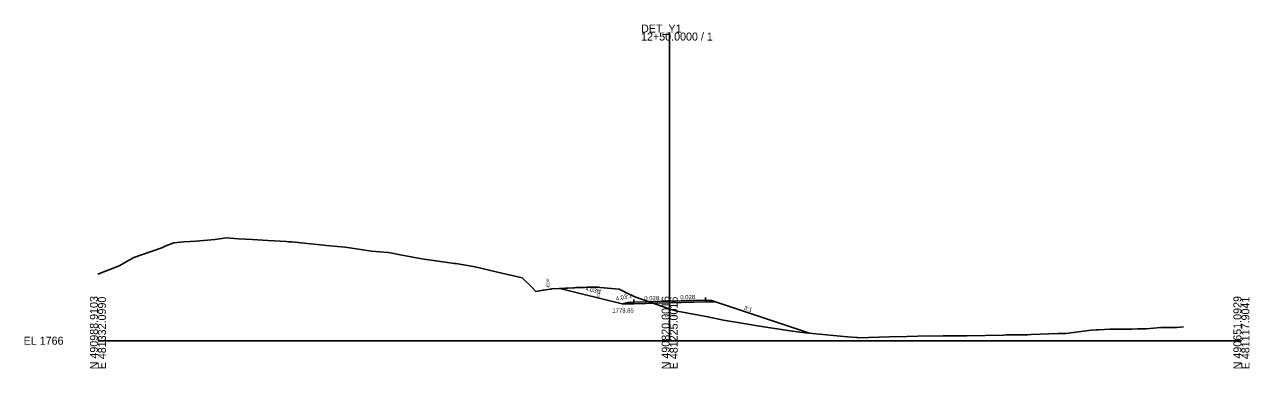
# Model space of a CAD drawing. Extents: x -26 to 403, y -10 to 3149.
# Drawn here: x -25.7 to 402.8, y 2490.3 to 2610.5 of the extents above; entities that cross this region are included whole.
import ezdxf

# ---------------------------------------------------------------- set-up
doc = ezdxf.new("R2010")
doc.units = 0
for name, color, linetype in [('Exist Cross Section Cell', 7, 'Continuous'), ('Exist XS Center Line Elevation Label', 7, 'Continuous'), ('Exist XS Ground Line', 7, 'Continuous'), ('Prop XS Ditch Slope Text', 7, 'Continuous'), ('Prop XS Ditch Standard Text', 7, 'Continuous'), ('Prop XS Dump Level', 7, 'Continuous'), ('Prop XS EOT Tick Mark', 7, 'Continuous'), ('Prop XS Finish Grade', 7, 'Continuous'), ('Prop XS Finish Grade Earthwork', 7, 'Continuous'), ('Prop XS Finish Grade Pavement', 7, 'Continuous'), ('Prop XS Pvmt Edge Slope', 7, 'Continuous'), ('Prop XS SE Text', 7, 'Continuous'), ('Prop XS Side Slope Text', 7, 'Continuous'), ('Prop XS Subgrade Earthwork', 7, 'Continuous'), ('Scratch_Level_3', 7, 'Continuous'), ('Scratch_Level_4', 7, 'Continuous')]:
    doc.layers.add(name, color=color, linetype=linetype)

msp = doc.modelspace()

# ---------------------------------------------------------------- linework, layer by layer
at = {"layer": 'Exist Cross Section Cell'}
for p, q in [((200, 2500), (200, 2607.66)), ((0, 2500), (200, 2500)), ((200, 2500), (400, 2500))]:
    msp.add_line(p, q, dxfattribs=at)
at = {"layer": 'Exist XS Ground Line'}
msp.add_lwpolyline([(0, 2523.29), (7.41, 2526.21), (12.5, 2529.05), (22.4, 2532.43), (23.73, 2533.18), (26.6, 2534.19), (30.1, 2534.52), (34.41, 2534.81), (40.84, 2535.39), (44.94, 2535.89), (49.16, 2535.61), (54.1, 2535.36), (59.43, 2535.01), (65.94, 2534.63), (66.68, 2534.58), (67.84, 2534.49), (77.79, 2533.55), (81.17, 2533.19), (86.52, 2532.68), (89.63, 2532.26), (95.67, 2531.27), (101.47, 2530.8), (102.92, 2530.61), (105.19, 2530.14), (110.16, 2529.17), (113.32, 2528.57), (117.41, 2527.97), (123.87, 2527.11), (124.66, 2526.99), (125.16, 2526.92), (131.91, 2525.79), (139.76, 2523.98), (148.37, 2521.98), (151.65, 2518.81), (153.18, 2517.21), (155.79, 2517.63), (157.43, 2517.95), (158.44, 2518.04), (158.77, 2518.07), (161.35, 2518.23), (163.43, 2518.33), (164.3, 2518.36), (166.37, 2518.5), (166.88, 2518.53), (167.28, 2518.55), (168.07, 2518.58), (170.19, 2518.64), (171.17, 2518.66), (172.73, 2518.67), (173.15, 2518.67), (173.46, 2518.67), (175.06, 2518.69), (175.62, 2518.64), (182.38, 2517.96), (184.67, 2516.86), (187.76, 2515.29), (200.16, 2511.03), (201.31, 2510.64), (202.68, 2510.37), (213.3, 2508.29), (218.87, 2507.21), (227.29, 2505.79), (231.43, 2505.06), (242.15, 2503.48), (245.53, 2502.95), (247.48, 2502.77), (262.17, 2501.4), (265.55, 2501.09), (265.92, 2501.05), (276.79, 2501.33), (282.93, 2501.49), (290.75, 2501.66), (293.57, 2501.64), (295.68, 2501.65), (300.9, 2501.65), (303.95, 2501.73), (316.85, 2501.99), (317.74, 2502.01), (321.47, 2502), (325.13, 2502.08), (326.43, 2502.12), (335.8, 2502.58), (338.58, 2502.56), (347.4, 2503.64), (349.34, 2503.86), (350.18, 2503.84), (353.93, 2504.01), (361.69, 2504.09), (363.63, 2504.2), (366.69, 2504.2), (371.86, 2504.61), (377.44, 2504.67), (379.75, 2504.9)], dxfattribs=at)
at = {"layer": 'Prop XS Dump Level'}
for p, q in [((187.42, 2513.43), (200, 2513.79)), ((200, 2513.79), (212.58, 2514.14))]:
    msp.add_line(p, q, dxfattribs=at)
at = {"layer": 'Prop XS EOT Tick Mark'}
for p, q in [((187.42, 2513.43), (187.42, 2514.43)), ((212.58, 2514.14), (212.58, 2515.14))]:
    msp.add_line(p, q, dxfattribs=at)
at = {"layer": 'Prop XS Finish Grade'}
for p, q in [((185.4, 2513.35), (183.38, 2512.85)), ((187.42, 2513.43), (185.4, 2513.35)), ((212.58, 2514.14), (214.59, 2514.06)), ((214.59, 2514.06), (216.33, 2513.48))]:
    msp.add_line(p, q, dxfattribs=at)
at = {"layer": 'Prop XS Finish Grade Earthwork'}
for p, q in [((183.38, 2512.85), (161.62, 2518.25)), ((216.33, 2513.48), (248.86, 2502.64))]:
    msp.add_line(p, q, dxfattribs=at)
at = {"layer": 'Prop XS Finish Grade Pavement'}
for p, q in [((187.42, 2513.43), (200, 2513.79)), ((200, 2513.79), (212.58, 2514.14))]:
    msp.add_line(p, q, dxfattribs=at)
at = {"layer": 'Prop XS Pvmt Edge Slope'}
for p, q in [((187.42, 2513.43), (186.85, 2512.87)), ((212.58, 2514.14), (213.15, 2513.58))]:
    msp.add_line(p, q, dxfattribs=at)
at = {"layer": 'Prop XS Subgrade Earthwork'}
for p, q in [((186.85, 2512.87), (183.38, 2512.85)), ((187.42, 2512.89), (186.85, 2512.87)), ((200, 2513.25), (187.42, 2512.89)), ((212.58, 2513.6), (200, 2513.25)), ((212.58, 2513.6), (216.33, 2513.48))]:
    msp.add_line(p, q, dxfattribs=at)
at = {"layer": 'Scratch_Level_4'}
for p, q in [((183.38, 2512.85), (161.62, 2518.25)), ((185.4, 2513.35), (183.38, 2512.85)), ((185.4, 2513.35), (186.33, 2513.39)), ((187.42, 2513.43), (186.33, 2513.39)), ((187.42, 2513.43), (200, 2513.79)), ((200, 2513.79), (212.58, 2514.14)), ((212.58, 2514.14), (213.66, 2514.1)), ((213.66, 2514.1), (214.59, 2514.06)), ((214.59, 2514.06), (248.86, 2502.64))]:
    msp.add_line(p, q, dxfattribs=at)

# ---------------------------------------------------------------- texts
at = {"layer": 'Exist Cross Section Cell'}
for s, p in [('DET_Y1', (190, 2607.66)), ('12+50.0000 / 1', (190, 2604.86)), ('EL 1766', (-26, 2498.6))]:
    msp.add_text(s, height=2.8, dxfattribs=at).set_placement(p)
for s, p in [('N 490988.9103', (0, 2490)), ('E 481332.0990', (2.8, 2490)), ('N 490820.0016', (200, 2490)), ('E 481225.0016', (202.8, 2490)), ('N 490651.0929', (400, 2490)), ('E 481117.9041', (402.8, 2490))]:
    msp.add_text(s, height=2.8, rotation=90, dxfattribs=at).set_placement(p)
at = {"layer": 'Exist XS Center Line Elevation Label'}
msp.add_text('1777.09', height=0.75, dxfattribs=at).set_placement((198.33, 2508.34))
at = {"layer": 'Prop XS Ditch Slope Text'}
msp.add_text('4.03:1', height=1.5, rotation=13.9266, dxfattribs=at).set_placement((181.36, 2513.84))
at = {"layer": 'Prop XS Ditch Standard Text'}
msp.add_text('1778.85', height=1.5, dxfattribs=at).set_placement((179.95, 2509.85))
at = {"layer": 'Prop XS SE Text'}
for p in [(191.15, 2514.03), (203.73, 2514.39)]:
    msp.add_text('0.028', height=1.5, rotation=1.6229, dxfattribs=at).set_placement(p)
at = {"layer": 'Prop XS Side Slope Text'}
for s, rotation, p in [('4.03:1', 346.0734, (170.37, 2517.62)), ('3:1', 341.5651, (225.85, 2510.92))]:
    msp.add_text(s, height=1.5, rotation=rotation, dxfattribs=at).set_placement(p)
at = {"layer": 'Scratch_Level_3'}
for p in [(157.93, 2518.36), (175.56, 2514.91)]:
    msp.add_text('-EOP', height=1, rotation=90, dxfattribs=at).set_placement(p)

doc.saveas('drawing.dxf')
